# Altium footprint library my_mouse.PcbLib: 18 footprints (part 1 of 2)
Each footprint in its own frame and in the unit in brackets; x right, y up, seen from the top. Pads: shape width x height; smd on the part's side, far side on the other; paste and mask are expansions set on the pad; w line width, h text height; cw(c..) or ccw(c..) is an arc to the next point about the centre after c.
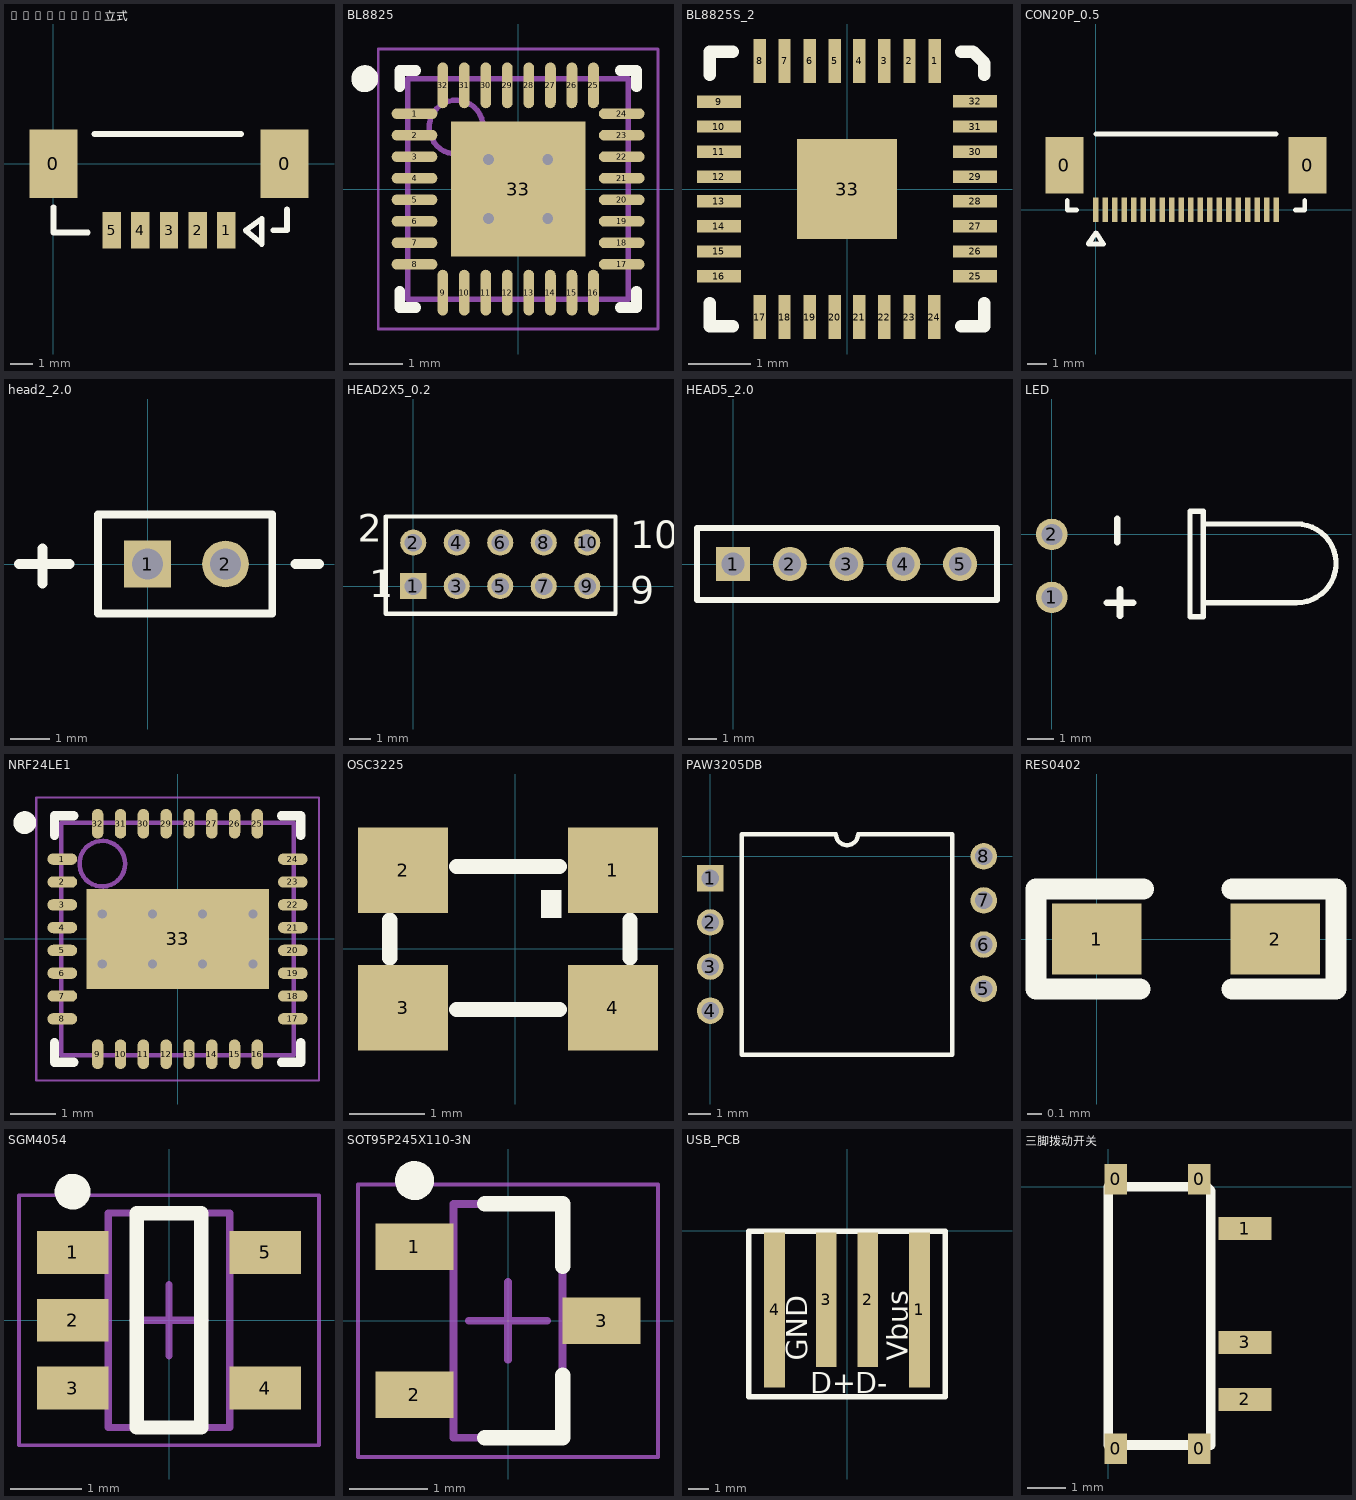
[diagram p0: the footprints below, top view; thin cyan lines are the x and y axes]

## 5P_1.25_立式 [mm]
pads (7):
  rect 2.1x3 smd: 0(0,0) 0(10.1,0)
  rect 0.8x1.6 smd: 1(7.55,-2.9) 2(6.3,-2.9) 3(5.05,-2.9) 4(3.8,-2.9) 5(2.55,-2.9)
Top Overlay:
  lines w0.254: 0,-1.9 0,-3 1.5,-3 ; 1.8,1.3 8.2,1.3 ; 9.6,-2.9 10.2,-2.9 10.2,-2 ; 8.4,-2.9 9.1,-2.4 9.1,-3.5 8.4,-2.9

## BL8825 [mm] "QFN, 32-Leads, Body 4.00x4.00mm, Pitch 0.40mm, Thermal Pad 2.65x2.65mm, IPC Medium Density"
height 0.8
pads (33):
  oval 0.85x0.2 smd: 1(-1.925,1.4) 2(-1.925,1) 3(-1.925,0.6) 4(-1.925,0.2) 5(-1.925,-0.2) 6(-1.925,-0.6) 7(-1.925,-1) 8(-1.925,-1.4) 17(1.925,-1.4) 18(1.925,-1) 19(1.925,-0.6) 20(1.925,-0.2) 21(1.925,0.2) 22(1.925,0.6) 23(1.925,1) 24(1.925,1.4)
  oval 0.2x0.85 smd: 9(-1.4,-1.925) 10(-1,-1.925) 11(-0.6,-1.925) 12(-0.2,-1.925) 13(0.2,-1.925) 14(0.6,-1.925) 15(1,-1.925) 16(1.4,-1.925) 25(1.4,1.925) 26(1,1.925) 27(0.6,1.925) 28(0.2,1.925) 29(-0.2,1.925) 30(-0.6,1.925) 31(-1,1.925) 32(-1.4,1.925)
  rect 2.5x2.5 smd: 33(0,0)
via 0.55,-0.55 diameter 0.5 hole 0.2
via -0.55,-0.55 diameter 0.5 hole 0.2
via 0.55,0.55 diameter 0.5 hole 0.2
via -0.55,0.55 diameter 0.5 hole 0.2
Top Overlay:
  circle w0.25: c-2.85,2.05 r0.125
  lines w0.2: -2.2,-1.9 -2.2,-2.2 -1.9,-2.2 ; -2.2,1.9 -2.2,2.2 -1.9,2.2 ; 1.9,-2.2 2.2,-2.2 2.2,-1.9 ; 1.9,2.2 2.2,2.2 2.2,1.9
Mechanical 13:
  circle w0.1: c-1.15,1.15 r0.5
  lines w0.1: -2.05,-2.05 2.05,-2.05 2.05,2.05 -2.05,2.05 -2.05,-2.05
Mechanical 15:
  lines w0.05: -2.6,-2.6 2.6,-2.6 2.6,2.6 -2.6,2.6 -2.6,-2.6
  lines w0.1: -0.5,0 0.5,0 ; 0,-0.5 0,0.5
3D body: height 0.8, standoff 0.01, extent -2.05,-2.05 2.05,2.05

## BL8825S_2 [mm]
pads (33):
  rect 0.2x0.7 smd: 1(1.4,2.05) 2(1,2.05) 3(0.6,2.05) 4(0.2,2.05) 5(-0.2,2.05) 6(-0.6,2.05) 7(-1,2.05) 8(-1.4,2.05) 17(-1.4,-2.05) 18(-1,-2.05) 19(-0.6,-2.05) 20(-0.2,-2.05) 21(0.2,-2.05) 22(0.6,-2.05) 23(1,-2.05) 24(1.4,-2.05)
  rect 0.7x0.2 smd: 9(-2.05,1.4) 10(-2.05,1) 11(-2.05,0.6) 12(-2.05,0.2) 13(-2.05,-0.2) 14(-2.05,-0.6) 15(-2.05,-1) 16(-2.05,-1.4) 25(2.05,-1.4) 26(2.05,-1) 27(2.05,-0.6) 28(2.05,-0.2) 29(2.05,0.2) 30(2.05,0.6) 31(2.05,1) 32(2.05,1.4)
  rect 1.6x1.6 smd: 33(0,0)
Top Overlay:
  lines w0.2: -2.2,-1.825 -2.2,-2.2 -1.825,-2.2 ; -2.2,1.825 -2.2,2.2 -1.825,2.2 ; 1.825,-2.2 2.2,-2.2 2.2,-1.825 ; 1.825,2.2 2.013,2.2 2.2,2.013 2.2,1.825

## CON20P_0.5 [mm]
pads (22):
  rect 2x3 smd: 0(-1.65,2.35) 0(11.15,2.35)
  rect 0.3x1.3 smd: 1(0,0) 2(0.5,0) 3(1,0) 4(1.5,0) 5(2,0) 6(2.5,0) 7(3,0) 8(3.5,0) 9(4,0) 10(4.5,0) 11(5,0) 12(5.5,0) 13(6,0) 14(6.5,0) 15(7,0) 16(7.5,0) 17(8,0) 18(8.5,0) 19(9,0) 20(9.5,0)
Top Overlay:
  lines w0.254: -1.5,0.5 -1.5,0 -1,0 ; 0,4 9.5,4 ; 10.5,0 11,0 11,0.5 ; -0.4,-1.8 0.4,-1.8 0,-1.2 -0.4,-1.8

## head2_2.0 [mm]
pads (2):
  rect 1.2x1.2 hole 0.8: 1(0,0)
  round 1.2 hole 0.8: 2(2,0)
Top Overlay:
  lines w0.2: -1.27,-1.27 -1.27,1.27 3.2,1.27 3.2,-1.27 -1.27,-1.27
  lines w0.254: -3.3,0 -2,0 ; -2.7,-0.5 -2.7,0.4 ; 3.8,0 4.4,0

## HEAD2X5_0.2 [mm]
pads (10):
  rect 1.2x1.2 hole 0.8: 1(0,0)
  round 1.2 hole 0.8: 2(0,2) 3(2,0) 4(2,2) 5(4,0) 6(4,2) 7(6,0) 8(6,2) 9(8,0) 10(8,2)
Top Overlay:
  lines w0.2: -1.27,-1.27 -1.27,3.2 9.3,3.2 9.3,-1.27 -1.27,-1.27
  text "2" at -2.54,2.032 h1.27
  text "1" at -2.032,-0.508 h1.27
  text "9" at 9.984,-0.808 h1.27
  text "10" at 9.984,1.732 h1.27

## HEAD5_2.0 [mm]
pads (5):
  rect 1.2x1.2 hole 0.8: 1(0,0)
  round 1.2 hole 0.8: 2(2,0) 3(4,0) 4(6,0) 5(8,0)
Top Overlay:
  lines w0.2: -1.27,-1.27 -1.27,1.27 9.3,1.27 9.3,-1.27 -1.27,-1.27

## LED [mm]
pads (2):
  round 1.2 hole 0.8: 1(0,-2.4) 2(0,0)
Top Overlay:
  lines w0.2: 5.827,-2.603 9.325,-2.603 ccw(c9.325,-1.103) 9.325,0.397 5.827,0.397 ; 5.261,-3.135 5.769,-3.135 5.769,0.881 5.261,0.881 5.261,-3.135
  lines w0.254: 2.1,-2.6 3.1,-2.6 ; 2.5,-0.3 2.5,0.6 ; 2.6,-3.1 2.6,-2.1

## NRF24LE1 [mm] "QFN, 32-Leads, Body 5.00x5.00mm, Pitch 0.50mm, Thermal Pad 4.00x2.20mm, IPC Medium Density"
height 0.8
pads (33):
  oval 0.65x0.25 smd: 1(-2.525,1.75) 2(-2.525,1.25) 3(-2.525,0.75) 4(-2.525,0.25) 5(-2.525,-0.25) 6(-2.525,-0.75) 7(-2.525,-1.25) 8(-2.525,-1.75) 17(2.525,-1.75) 18(2.525,-1.25) 19(2.525,-0.75) 20(2.525,-0.25) 21(2.525,0.25) 22(2.525,0.75) 23(2.525,1.25) 24(2.525,1.75)
  oval 0.25x0.65 smd: 9(-1.75,-2.525) 10(-1.25,-2.525) 11(-0.75,-2.525) 12(-0.25,-2.525) 13(0.25,-2.525) 14(0.75,-2.525) 15(1.25,-2.525) 16(1.75,-2.525) 25(1.75,2.525) 26(1.25,2.525) 27(0.75,2.525) 28(0.25,2.525) 29(-0.25,2.525) 30(-0.75,2.525) 31(-1.25,2.525) 32(-1.75,2.525)
  rect 4x2.2 smd: 33(0,0)
via -1.65,0.55 diameter 0.5 hole 0.2
via -0.55,0.55 diameter 0.5 hole 0.2
via 0.55,0.55 diameter 0.5 hole 0.2
via 1.65,0.55 diameter 0.5 hole 0.2
via -1.65,-0.55 diameter 0.5 hole 0.2
via -0.55,-0.55 diameter 0.5 hole 0.2
via 0.55,-0.55 diameter 0.5 hole 0.2
via 1.65,-0.55 diameter 0.5 hole 0.2
Top Overlay:
  circle w0.25: c-3.35,2.55 r0.125
  lines w0.2: -2.7,-2.275 -2.7,-2.7 -2.275,-2.7 ; -2.7,2.275 -2.7,2.7 -2.275,2.7 ; 2.275,-2.7 2.7,-2.7 2.7,-2.275 ; 2.275,2.7 2.7,2.7 2.7,2.275
Mechanical 13:
  circle w0.1: c-1.65,1.65 r0.5
  lines w0.1: -2.55,-2.55 -2.55,2.55 2.55,2.55 2.55,-2.55 -2.55,-2.55
Mechanical 15:
  lines w0.05: -3.1,-3.1 -3.1,3.1 3.1,3.1 3.1,-3.1 -3.1,-3.1
  lines w0.1: -0.5,0 0.5,0 ; 0,-0.5 0,0.5
3D body: height 0.8, standoff 0.01, extent -2.55,-2.55 2.55,2.55

## OSC3225 [mm]
pads (4):
  rect 1.2x1.143 smd: 1(1.298,1.047) 2(-1.496,1.047) 3(-1.496,-0.782) 4(1.298,-0.782)
Top Overlay:
  region: 0.613,0.787 0.338,0.787 0.338,0.412 0.613,0.412
  lines w0.203: -1.674,-0.122 -1.674,0.386 ; -0.785,-0.808 0.587,-0.808 ; -0.785,1.097 0.587,1.097 ; 1.527,-0.122 1.527,0.386

## PAW3205DB [mm]
pads (8):
  rect 1.2x1.2 hole 0.8: 1(0,-1)
  round 1.2 hole 0.8: 2(0,-3) 3(0,-5) 4(0,-7) 5(12.4,-6) 6(12.4,-4) 7(12.4,-2) 8(12.4,0)
Top Overlay:
  lines w0.2: 1.435,-9 10.965,-9 10.965,1 6.7,1 cw(c6.2,1) 5.7,1 1.435,1 1.435,-9

## RES0402 [mil]
pads (2):
  rect 25x20 smd: 1(0,0) 2(50,0)
Top Overlay:
  lines w6: 12,-14 -17,-14 -17,14 13,14 ; 38,-14 67,-14 67,14 38,14

## SGM4054 [mm]
pads (5):
  rect 1x0.6 smd: 1(-1.35,0.95) 2(-1.35,0) 3(-1.35,-0.95) 4(1.35,-0.95) 5(1.35,0.95)
Top Overlay:
  circle w0.25: c-1.35,1.8 r0.125
  lines w0.2: -0.45,-1.5 -0.45,1.5 0.45,1.5 0.45,-1.5 -0.45,-1.5
Mechanical 13:
  lines w0.1: -0.85,-1.5 0.85,-1.5 0.85,1.5 -0.85,1.5 -0.85,-1.5
Mechanical 15:
  lines w0.05: -2.1,-1.75 2.1,-1.75 2.1,1.75 -2.1,1.75 -2.1,-1.75
  lines w0.1: -0.5,0 0.5,0 ; 0,-0.5 0,0.5
3D body: height 0.9, standoff 0.1, extent -0.85,-1.5 0.85,1.5

## SOT95P245X110-3N [mm] "SOT23, 3-Leads, Body 2.90x2.45mm, Pitch 0.95mm, IPC Medium Density"
height 1.1
pads (3):
  rect 1x0.6 smd: 1(-1.2,0.95) 2(-1.2,-0.95) 3(1.2,0)
Top Overlay:
  circle w0.25: c-1.2,1.8 r0.125
  lines w0.2: -0.3,-1.5 0.7,-1.5 0.7,-0.7 ; -0.3,1.5 0.7,1.5 0.7,0.7
Mechanical 13:
  lines w0.1: -0.7,-1.5 -0.7,1.5 0.7,1.5 0.7,-1.5 -0.7,-1.5
Mechanical 15:
  lines w0.05: -1.925,-1.75 -1.925,1.75 1.925,1.75 1.925,-1.75 -1.925,-1.75
  lines w0.1: -0.5,0 0.5,0 ; 0,-0.5 0,0.5
3D body: height 1.1, standoff 0.05, extent -0.7,-1.5 0.7,1.5

## USB_PCB [mm]
pads (4):
  rect 1x7.5 smd: 1(3.5,-3.825) 4(-3.5,-3.825)
  rect 1x6.5 smd: 2(1,-3.325) 3(-1,-3.325)
Top Overlay:
  lines w0.254: -4.75,-8.025 4.75,-8.025 4.75,-0.025 -4.75,-0.025 -4.75,-8.025
  text "D+" at -1.775,-7.85 h1
  text "D-" at 0.4,-7.85 h1
  text "Vbus" at 2.925,-6.275 h1
  text "GND" at -1.925,-6.275 h1

## 三脚拨动开关 [mm]
pads (7):
  rect 0.6x0.8 all layers, no hole: 0(0.2,-6.9) 0(0.2,0.2) 0(2.4,-6.9) 0(2.4,0.2)
  rect 1.4x0.6 all layers, no hole: 1(3.6,-1.1) 2(3.6,-5.6) 3(3.6,-4.1)
Top Overlay:
  lines w0.254: 0,-6.8 2.7,-6.8 2.7,-0.1 2.6,0 0,0 0,-6.8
